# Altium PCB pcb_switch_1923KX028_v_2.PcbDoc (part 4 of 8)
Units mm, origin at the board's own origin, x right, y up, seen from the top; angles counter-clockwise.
Board outline 297.2 x 112.05 mm, 6 copper layers (Component Side, GND Layer 1, Inner Layer 1, Inner Layer 2, GND Layer 2, Solder Side), stack 1.578 mm thick; 545 components, 377 nets, 3174 pads, 1537 vias.
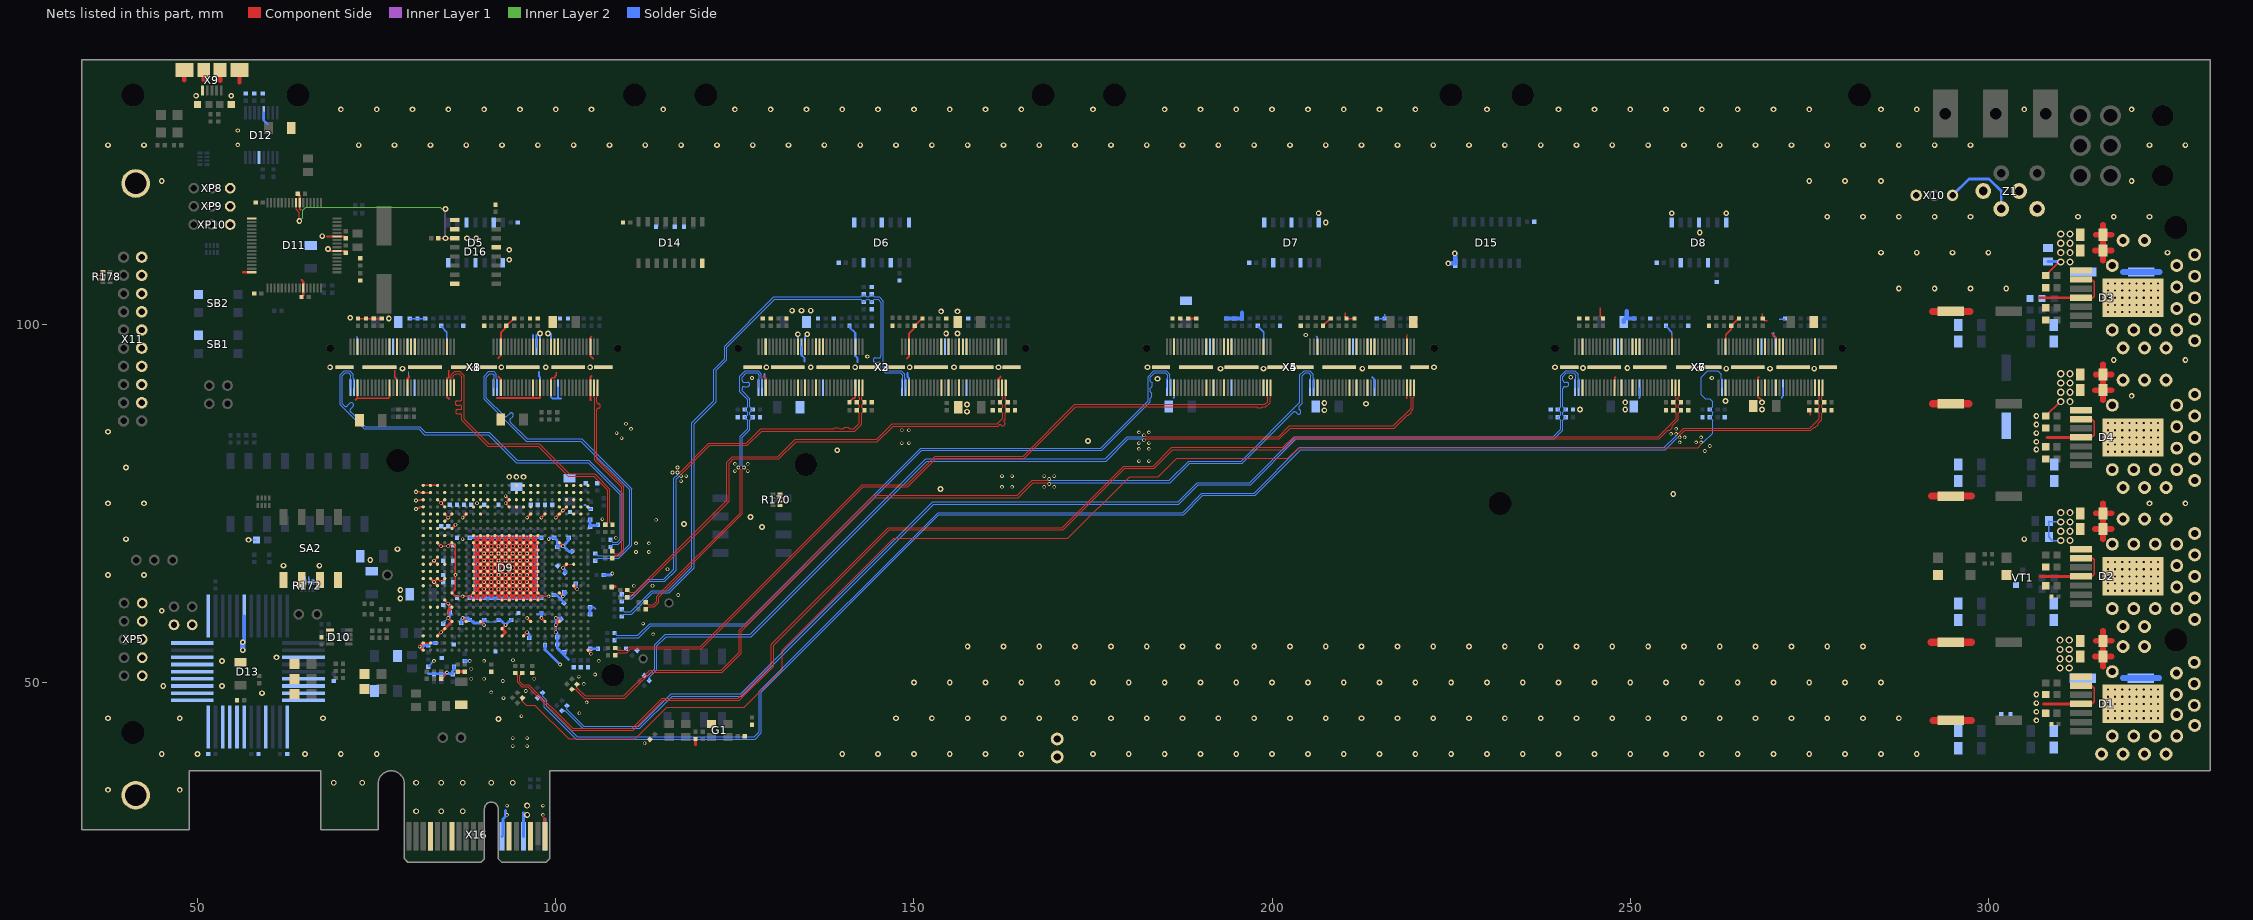
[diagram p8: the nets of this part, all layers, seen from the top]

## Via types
v1: diameter 0.8, hole 0.4, Component Side to Solder Side, tented both sides, 884 vias
v2: diameter 0.5, hole 0.3, Component Side to Solder Side, tented both sides, 269 vias
v3: diameter 1, hole 0.6, Component Side to Solder Side, tented both sides, 95 vias
v4: diameter 0.5/0.5/0.3/0.3/0.5/0.5 (per signal layer), hole 0.3, Component Side to Solder Side, tented both sides, 80 vias
v5: diameter 0.5/0.3/0.3/0.5/0.3/0.5 (per signal layer), hole 0.3, Component Side to Solder Side, tented both sides, 37 vias
v6: diameter 0.5/0.3/0.3/0.3/0.3/0.5 (per signal layer), hole 0.3, Component Side to Solder Side, tented both sides, 34 vias
v7: diameter 0.5/0.5/0.5/0.3/0.5/0.5 (per signal layer), hole 0.3, Component Side to Solder Side, tented both sides, 29 vias
v8: diameter 0.5, hole 0.3, Component Side to Solder Side, 25 vias
v9: diameter 0.5/0.3/0.5/0.3/0.3/0.5 (per signal layer), hole 0.3, Component Side to Solder Side, tented both sides, 25 vias
v10: diameter 0.5/0.5/0.3/0.5/0.5/0.5 (per signal layer), hole 0.3, Component Side to Solder Side, tented both sides, 19 vias
v11: diameter 0.6, hole 0.3, Component Side to Solder Side, tented both sides, 14 vias
v12: diameter 0.8, hole 0.5, Component Side to Solder Side, tented both sides, 11 vias
v13: diameter 0.5/0.3/0.5/0.5/0.3/0.5 (per signal layer), hole 0.3, Component Side to Solder Side, tented both sides, 7 vias
v14: diameter 0.8, hole 0.4, Component Side to Solder Side, 5 vias
v15: diameter 0.5/0.5/0.5/0.5/0.5/0.5 (per signal layer), hole 0.3, Component Side to Solder Side, tented both sides, 2 vias
v16: diameter 0.8, hole 0.5, Component Side to Solder Side, 1 vias

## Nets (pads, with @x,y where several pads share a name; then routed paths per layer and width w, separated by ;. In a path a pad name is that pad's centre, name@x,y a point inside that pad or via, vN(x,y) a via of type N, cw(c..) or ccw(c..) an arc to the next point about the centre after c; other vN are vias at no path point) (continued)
GND: C1.2 C2.2 C3.2 C4.2 C5.2 C6.2 C7.2 C8.2 C9.2 C10.2 C11.2 C12.2 C13.2 C14.2 C15.2 C16.2 C17.2 C18.1 C19.2 C20.2 C21.2 C22.2 C23.2 C24.2 C25.2 C26.2 C27.2 C28.2 C29.2 C30.2 C31.1 C32.1 C33.1 C34.1 C35.2 C36.2 C37.2 C38.2 C39.2 C40.2 C41.2 C42.2 C43.1 C44.2 C45.2 C46.2 C47.2 C50.2 C51.2 C52.2 C53.2 C56.2 C57.1 C58.2 C59.2 C61.1 C63.1 C65.2 C66.2 C69.2 C70.2 C71.2 C74.2 C75.2 C78.2 C83.2 C85.2 C94.1 C95.1 C96.1 C101.2 C102.2 C103.2 C104.2 C105.2 C106.2 C107.2 C108.2 C109.2 C110.2 C111.2 C112.2 C113.2 C114.2 C115.2 C116.1 C117.1 C118.1 C119.1 C121.1 C122.1 C123.1 C124.1 C125.2 C126.1 C127.2 C128.2 C129.2 C130.2 C131.2 C132.2 C133.2 C134.2 C135.2 C136.2 C137.2 C138.2 C139.2 C140.2 C141.2 C142.2 C143.2 C144.2 C145.2 C146.2 C147.2 C148.2 C149.2 C150.2 C151.2 C152.2 C153.2 C154.2 C155.2 C156.2 C157.2 C158.2 C159.2 C160.2 C161.2 C162.2 C163.2 C164.2 C165.2 C166.2 C167.2 C168.2 C169.2 C170.2 C171.2 C172.2 C173.2 C174.2 C175.2 C176.2 C177.2 C178.2 C179.2 C180.2 C181.2 C182.2 C183.2 C184.2 C187.2 C188.2 C189.2 C190.2 C193.2 C194.2 C195.2 C196.2 C197.2 C198.2 C199.2 C200.2 C201.2 C202.2 C203.2 C204.2 C205.2 C206.2 C207.2 C208.2 C209.2 C210.2 C211.2 C212.2 C213.2 C214.2 C215.2 C216.2 C217.2 C218.2 C219.2 C220.2 C221.2 C222.2 C223.2 C224.2 C225.2 C226.2 C227.1 C228.2 C229.2 C230.2 C231.2 C232.2 C233.2 C234.2 C235.2 C236.2 C237.2 C238.2 C239.1 D1.2 D1.4 D1.8 D2.2 D2.4 D2.8 D3.2 D3.4 D3.8 D4.2 D4.4 D4.8 D5.1 D5.4 D5.7 D5.10 D5.13 D6.1 D6.4 D6.7 D6.10 D6.13 D7.1 D7.4 D7.7 D7.10 D7.13 D8.1 D8.4 D8.7 D8.10 D8.13 D9.A1 D9.A2 D9.A3 D9.A7 D9.A8 D9.A9 D9.A14 D9.A15 D9.A16 D9.A17 D9.A21 D9.A22 D9.A23 D9.A24 D9.AA4 D9.AA12 D9.AB1 D9.AB3 D9.AB12 D9.AB15 D9.AC1 D9.AC2 D9.AD1 D9.AD24 D9.B1 D9.B2 D9.B4 D9.B8 D9.B9 D9.B14 D9.B15 D9.B16 D9.B17 D9.B20 D9.B21 D9.B22 D9.B23 D9.C1 D9.C3 D9.C4 D9.C7 D9.C8 D9.C9 D9.C10 D9.C11 D9.C13 D9.C14 D9.C15 D9.C16 D9.C20 D9.C21 D9.C22 D9.C23 D9.D1 D9.D4 D9.D8 D9.D9 D9.D10 D9.D13 D9.D14 D9.D15 D9.D16 D9.D20 D9.D21 D9.D22 D9.D23 D9.D24 D9.E1 D9.E2 D9.E3 D9.E4 D9.E5 D9.E7 D9.E9 D9.E16 D9.E18 D9.E20 D9.E22 D9.E23 D9.F1 D9.F2 D9.F3 D9.F4 D9.G2 D9.G3 D9.G4 D9.G5 D9.H1 D9.H3 D9.H4 D9.H8 D9.H9 D9.H10 D9.H11 D9.H12 D9.H13 D9.H14 D9.H15 D9.H16 D9.H17 D9.J3 D9.J5 D9.J8 D9.J9 D9.J10 D9.J11 D9.J12 D9.J13 D9.J14 D9.J15 D9.J16 D9.J17 D9.J20 D9.K8 D9.K9 D9.K10 D9.K11 D9.K12 D9.K13 D9.K14 D9.K15 D9.K16 D9.K17 D9.L1 D9.L3 D9.L8 D9.L9 D9.L10 D9.L11 D9.L12 D9.L13 D9.L14 D9.L15 D9.L16 D9.L17 D9.M1 D9.M2 D9.M3 D9.M4 D9.M8 D9.M9 D9.M10 D9.M11 D9.M12 D9.M13 D9.M14 D9.M15 D9.M16 D9.M17 D9.M21 D9.M22 D9.N1 D9.N2 D9.N3 D9.N8 D9.N9 D9.N10 D9.N11 D9.N12 D9.N13 D9.N14 D9.N15 D9.N16 D9.N17 D9.P1 D9.P2 D9.P3 D9.P4 D9.P8 D9.P9 D9.P10 D9.P11 D9.P12 D9.P13 D9.P14 D9.P15 D9.P16 D9.P17 D9.R1 D9.R3 D9.R8 D9.R9 D9.R10 D9.R11 D9.R12 D9.R13 D9.R14 D9.R15 D9.R16 D9.R17 D9.R22 D9.T5 D9.T8 D9.T9 D9.T10 D9.T11 D9.T12 D9.T13 D9.T14 D9.T15 D9.T16 D9.T17 D9.T20 D9.U4 D9.U8 D9.U9 D9.U12 D9.U13 D9.U14 D9.U15 D9.U16 D9.U17 D9.V2 D9.V3 D9.V5 D9.Y5 D9.Y7 D9.Y9 D9.Y16 D9.Y18 D9.Y20 D10.5 D11.11 D11.23 D11.27 D11.39 D11.49 D11.64 D12.5 D12.13 D13.1 D13.2 D13.3 D13.4 D13.6 D13.7 D13.8 D13.9 D13.10 D13.11 D13.12 D13.13 D13.15 D13.16 D13.21 D13.30 D13.33 D13.34 D13.35 D13.36 D13.37 D13.40 D14.8 D15.8 D16.1 D16.2 D16.8 D16.13 G1.2 pad.0@41.35,34.25 pad.0@41.35,119.65 pad.0@170,39.6 pad.0@170,42.1 pad.0@315.8,40 pad.0@317.3,42.5 pad.0@317.3,51.5 pad.0@317.3,60.3 pad.0@317.3,69.3 pad.0@317.3,79.7 pad.0@317.3,88.7 pad.0@317.3,99.2 pad.0@317.3,108.2 pad.0@318.8,40 pad.0@318.8,55 pad.0@318.8,57.8 pad.0@318.8,72.8 pad.0@318.8,77.2 pad.0@318.8,92.2 pad.0@318.8,96.7 pad.0@318.8,111.7 pad.0@320.3,42.5 pad.0@320.3,60.3 pad.0@320.3,69.3 pad.0@320.3,79.7 pad.0@320.3,99.2 pad.0@321.8,40 pad.0@321.8,55 pad.0@321.8,57.8 pad.0@321.8,72.8 pad.0@321.8,77.2 pad.0@321.8,92.2 pad.0@321.8,96.7 pad.0@321.8,111.7 pad.0@323.3,42.5 pad.0@323.3,60.3 pad.0@323.3,69.3 pad.0@323.3,79.7 pad.0@323.3,99.2 pad.0@324.8,40 pad.0@324.8,72.8 pad.0@324.8,77.2 pad.0@324.8,92.2 pad.0@324.8,96.7 pad.0@326.3,42.5 pad.0@326.3,45.5 pad.0@326.3,60.3 pad.0@326.3,63.3 pad.0@326.3,66.3 pad.0@326.3,69.3 pad.0@326.3,79.7 pad.0@326.3,82.7 pad.0@326.3,85.7 pad.0@326.3,88.7 pad.0@326.3,99.2 pad.0@326.3,102.2 pad.0@326.3,105.2 pad.0@326.3,108.2 pad.0@326.25,48.3 pad.0@326.25,51.3 pad.0@328.8,44 pad.0@328.8,58.8 pad.0@328.8,61.8 pad.0@328.8,64.8 pad.0@328.8,67.8 pad.0@328.8,70.8 pad.0@328.8,78.2 pad.0@328.8,81.2 pad.0@328.8,84.2 pad.0@328.8,87.2 pad.0@328.8,90.2 pad.0@328.8,97.7 pad.0@328.8,100.7 pad.0@328.8,103.7 pad.0@328.8,106.7 pad.0@328.8,109.7 pad.0@328.75,46.8 pad.0@328.75,49.8 pad.0@328.75,52.8 R1.2 R2.1 R3.1 R4.1 R5.1 R21.2 R22.2 R23.2 R24.2 R35.2 R38.2 R39.2 R40.2 R42.2 R44.2 R45.2 R46.2 R48.2 R50.2 R52.2 R54.2 R56.2 R58.2 R62.2 R63.2 R64.2 R65.2 R70.2 R71.2 R78.2 R79.2 R80.2 R81.2 R82.2 R83.2 R86.2 R87.2 R94.1 R95.1 R96.2 R97.2 R105.2 R106.2 R107.2 R108.2 R114.2 R115.2 R118.1 R119.1 R120.1 R121.2 R123.2 R125.2 R127.2 R128.2 R129.2 R130.2 R132.2 R133.2 R135.2 R136.2 R137.2 R144.2 R146.2 R148.2 R149.2 R151.2 R155.2 R157.2 R159.2 R160.1 R166.2 R168.2 R170.1 R170.2 R170.3 R170.4 R172.5 R172.6 R172.7 R172.8 R178.1 R178.2 R178.3 R180.1 R187.2 R188.2 R190.2 R191.2 R192.2 R193.2 R194.2 R195.2 R197.2 R198.2 R200.2 R201.2 R202.2 R203.2 R205.2 R207.2 R214.2 R215.2 R216.2 R220.2 R221.2 R222.2 R223.2 R224.2 SA2.1 SA2.2 SA2.3 SA2.4 SB1.3 SB2.3 VD1.2 VD4.2 VD5.2 VD6.2 VD7.2 VD8.2 VD9.2 VT1.2 X1.5 X1.6 X1.23 X1.24 X1.27 X1.28 X1.33 X1.34 X1.36 X1.38 X1.55 X1.56 X1.65 X1.66 X1.83 X1.84 X1.87 X1.88 X1.93 X1.94 X1.96 X1.98 X1.115 X1.116 X1.121 X1.122 X1.123 X1.124 X1.125 X1.126 X1.127 X1.128 X2.5 X2.6 X2.23 X2.24 X2.27 X2.28 X2.33 X2.34 X2.36 X2.38 X2.55 X2.56 X2.65 X2.66 X2.83 X2.84 X2.87 X2.88 X2.93 X2.94 X2.96 X2.98 X2.115 X2.116 X2.121 X2.122 X2.123 X2.124 X2.125 X2.126 X2.127 X2.128 X3.5 X3.6 X3.23 X3.24 X3.27 X3.28 X3.33 X3.34 X3.36 X3.38 X3.55 X3.56 X3.65 X3.66 X3.83 X3.84 X3.87 X3.88 X3.93 X3.94 X3.96 X3.98 X3.115 X3.116 X3.121 X3.122 X3.123 X3.124 X3.125 X3.126 X3.127 X3.128 X4.5 X4.6 X4.23 X4.24 X4.27 X4.28 X4.33 X4.34 X4.36 X4.38 X4.55 X4.56 X4.65 X4.66 X4.83 X4.84 X4.87 X4.88 X4.93 X4.94 X4.96 X4.98 X4.115 X4.116 X4.121 X4.122 X4.123 X4.124 X4.125 X4.126 X4.127 X4.128 X5.5 X5.6 X5.23 X5.24 X5.27 X5.28 X5.33 X5.34 X5.36 X5.38 X5.55 X5.56 X5.65 X5.66 X5.83 X5.84 X5.87 X5.88 X5.93 X5.94 X5.96 X5.98 X5.115 X5.116 X5.121 X5.122 X5.123 X5.124 X5.125 X5.126 X5.127 X5.128 X6.5 X6.6 X6.23 X6.24 X6.27 X6.28 X6.33 X6.34 X6.36 X6.38 X6.55 X6.56 X6.65 X6.66 X6.83 X6.84 X6.87 X6.88 X6.93 X6.94 X6.96 X6.98 X6.115 X6.116 X6.121 X6.122 X6.123 X6.124 X6.125 X6.126 X6.127 X6.128 X7.5 X7.6 X7.23 X7.24 X7.27 X7.28 X7.33 X7.34 X7.36 X7.38 X7.55 X7.56 X7.65 X7.66 X7.83 X7.84 X7.87 X7.88 X7.93 X7.94 X7.96 X7.98 X7.115 X7.116 X7.121 X7.122 X7.123 X7.124 X7.125 X7.126 X7.127 X7.128 X8.5 X8.6 X8.23 X8.24 X8.27 X8.28 X8.33 X8.34 X8.36 X8.38 X8.55 X8.56 X8.65 X8.66 X8.83 X8.84 X8.87 X8.88 X8.93 X8.94 X8.96 X8.98 X8.115 X8.116 X8.121 X8.122 X8.123 X8.124 X8.125 X8.126 X8.127 X8.128 X9.5 X9.6 X9.7 X9.8 X9.9 X10.3 X11.4 X11.6 X11.8 X11.10 X11.12 X11.14 X11.16 X11.18 X11.20 X16.A4 X16.A12 X16.A15 X16.A18 X16.B4 X16.B7 X16.B13 X16.B16 X16.B18 XP1.2 XP3.2 XP5.2 XP5.4 XP5.6 XP5.8 XP5.10 XP8.3 XP9.3 XP10.3 Z1.4 Z1.5 Z1.6 | length 694.4
  Component Side w0.15: D9.M21@101.5,66.5 D9.M22@102.5,66.5 ; R170.2@131.3,75.25 132.05,75.25 ; R170.3@131.3,75.75 132.05,75.75
  Component Side w0.2: 36.05,106.35 R178.3@36.8,106.35 ; 36.05,106.85 R178.2@36.8,106.85 ; D11.39@64.25,116.95 64.25,116.15 64.5,115.9 ; SA2.3@67,64.37 SA2.3@67.07,64.3 ; 72,89.4 72.3,89.7 ; X1.5@72.315,91.135 72.315,89.715 72.3,89.7 ; R128.2@72.4,100.8 R129.2@73.5,100.8 R130.2@74.6,100.8 R132.2@75.7,100.8 ; X1.23@76.815,91.135 76.815,89.915 76.6,89.7 72.3,89.7 ; 77.5,93.6 77.5,92.6 77.815,92.285 X1.27@77.815,91.135 ; v11(80.5,74.2) 80.6,74.3 80.9,74.3 81.1,74.5 D9.D1@81.5,74.5 ; v11(80.5,75.4) 81,75.4 81.1,75.5 D9.C1@81.5,75.5 ; v11(80.5,76.6) 81,76.6 81.1,76.5 D9.B1@81.5,76.5 D9.B2@82.5,76.5 ; D9.AC1@81.5,55.5 D9.AC2@82.5,55.5 ; D9.A1@81.5,77.5 D9.A2@82.5,77.5 D9.A3@83.5,77.5 ; D9.M2@82.5,66.5 D9.L3@83.5,67.5 ; v7(83,67) D9.M3@83.5,66.5 ; D9.P3@83.5,64.5 83.9,64.1 84.1,64.1 D9.P4@84.5,64.5 ; D9.C3@83.5,75.5 v2(84,75) ; R144.2@84,50.5 84.1,50.5 84.6,51 84.6,51.2 v7(84.8,51.4) ; v7(84,69) v7(85,69) ; D9.U4@84.5,61.5 v7(85,61) ; D9.F4@84.5,72.5 v7(85,73) ; D9.E4@84.5,73.5 v7(85,73) ; D9.D4@84.5,74.5 v2(84,75) ; D9.C4@84.5,75.5 v2(84,75) ; v4(85,59) 85,60 ; 85.035,93.6 85.035,92.635 84.815,92.415 X1.55@84.815,91.135 84.815,89.885 85.2,89.5 ; D9.J5@85.5,69.5 86,69 v4(86,65) 86,63 D9.T5@85.5,62.5 86,62 v4(87,62) 88,62 ; D9.E5@85.5,73.5 v7(85,73) ; D9.U8@88.5,61.5 88,62 ; D9.T8@88.5,62.5 88,62 ; v2(93,76) D9.C13@93.5,75.5 v2(93,75) D9.D13@93.5,74.5 ; R42.2@93.1,99.8 94.1,100.8 R133.2@94.2,100.8 ; D9.U17@97.5,61.5 98,62 ; D9.T17@97.5,62.5 98,62 ; v4(99,62) 98,62 ; X1.93@99.32,91.135 99.32,92.367 99.5,92.547 99.8,92.547 100.1,92.847 100.1,93.3 ; v4(100,57) v4(100,58) ; 105,98.3 104.82,98.12 X1.116@104.82,96.865 104.82,95.58 105.2,95.2 105.3,95.2 ; R21.2@141,89.2 141.5,89.7 141.7,89.7 141.815,89.815 X2.55@141.815,91.135 ; R48.2@150.1,99.8 151.1,100.8 R149.2@151.2,100.8 ; R79.2@207.1,99.8 208.1,100.8 R197.2@208.2,100.8 ; 210.2,101.6 210.2,101 R198.2@210.4,100.8 R201.2@211.5,100.8 ; 218.82,89.58 X4.115@218.82,91.135 ; X4.116@218.82,96.865 218.82,98.42 218.9,98.5 ; 245.8,102.3 245.8,101.2 R193.2@246.2,100.8 ; X6.23@247.815,91.135 247.815,92.515 248,92.7 ; X6.56@255.815,96.865 255.815,98.415 255.9,98.5 ; X6.66@263.32,96.865 263.32,98.52 264.1,99.3 R83.2@264.1,99.8 265.1,100.8 R200.2@265.2,100.8 ; 268,92.7 267.82,92.52 X6.83@267.82,91.135 267.82,89.88 268.2,89.5 ; 268.4,101.5 268.4,100.9 R203.2@268.5,100.8 268.8,100.5 269.1,100.5 ; R86.2@275,88 275.1,87.9 275.1,87.3 ; D3.2@312.86,106.3 D3.2@312.92,106.24 314.46,106.24 314.8,105.9 314.8,103.9 314.5,103.6 313.02,103.6 D3.4@312.92,103.7 ; D1.4@312.92,47 314.5,47 314.8,47.3 314.8,49.2 314.46,49.54 D1.2@312.92,49.54 ; D2.4@312.92,64.8 314.5,64.8 314.8,65.1 314.8,67.1 314.56,67.34 D2.2@312.92,67.34 ; D4.4@312.92,84.2 314.4,84.2 314.8,84.6 314.8,86.4 314.46,86.74 D4.2@312.92,86.74
  Component Side w0.28: X1.33@79.315,91.135 79.315,92.415 79.5,92.6 79.5,92.8 ; 91.8,89.7 97.82,89.7 X1.87@97.82,91.135 ; 92,92.7 92.32,92.38 X1.65@92.32,91.135 ; 92,95.3 92.32,95.62 X1.66@92.32,96.865 92.32,98.82 93.1,99.6 R42.2@93.1,99.8 ; 96.82,89.7 X1.83@96.82,91.135 ; 104.9,89.4 104.82,89.48 X1.115@104.82,91.135 104.82,92.62 105,92.8 ; 129,92.7 129.315,92.385 X2.5@129.315,91.135 ; 149,95.2 149.32,95.52 X2.66@149.32,96.865 149.32,98.72 150,99.4 150,99.7 R48.2@150.1,99.8 ; X2.115@161.82,91.135 161.82,92.42 162.1,92.7 ; R191.2@188.3,100.8 R194.2@189.4,100.8 ; 269.8,98.7 270.32,98.18 X6.94@270.32,96.865
  Component Side w0.3: 56.35,107.25 D11.64@57.55,107.25 ; C126.1@64,118.2 64.25,117.95 D11.39@64.25,116.95 ; C123.1@64.5,103.8 64.75,104.05 D11.11@64.75,105.05 64.75,105.95 64.5,106.2 ; 68.05,112.25 D11.27@69.45,112.25 70.45,112.25 C119.1@70.7,112 ; v1(68.2,110.5) 68.45,110.25 D11.23@69.45,110.25 70.45,110.25 C118.1@70.7,110
  Component Side w0.4: D9.AD1@81.5,54.5 v2(81,55) D9.AC1@81.5,55.5 ; D9.P2@82.5,64.5 v7(83,64) ; D9.AB3@83.5,56.5 D9.Y5@85.5,58.5 v4(85,59) ; D9.R3@83.5,63.5 v7(83,64) ; D9.P3@83.5,64.5 v7(83,64) ; D9.J3@83.5,69.5 v7(84,69) ; 85,60 D9.V5@85.5,60.5 v7(85,61) ; v7(85,69) D9.J5@85.5,69.5 ; D9.G5@85.5,71.5 v4(86,72) ; C214.2@86.3,51.5 C205.2@87.3,51.5 ; v4(87,59) D9.Y7@87.5,58.5 ; v4(87,73) D9.E7@87.5,73.5 ; D9.U8@88.5,61.5 89,62 ; D9.H8@88.5,70.5 89,70 ; D9.Y9@89.5,58.5 v4(90,58) ; v4(91,64) D9.R11@91.5,63.5 ; v4(91,66) D9.N11@91.5,65.5 ; v4(91,67) D9.M11@91.5,66.5 ; v4(91,68) D9.L11@91.5,67.5 ; D9.AB12@92.5,56.5 93,57 D9.AA12@92.5,57.5 v4(93,58) ; D9.AB15@95.5,56.5 v4(96,57) ; v4(96,59) D9.Y16@96.5,58.5 ; v4(96,67) D9.M16@96.5,66.5 ; v4(96,69) D9.K16@96.5,68.5 ; v4(96,73) D9.E16@96.5,73.5 ; D9.U17@97.5,61.5 97,62 ; D9.H17@97.5,70.5 97,70 ; v4(98,59) D9.Y18@98.5,58.5 ; v4(98,73) D9.E18@98.5,73.5 ; 98.4,31 98.4,28.6 X16.B18@98.5,28.5 ; v4(100,58) D9.Y20@100.5,58.5 v4(100,59) ; v7(100,73) v2(101,74) D9.D21@101.5,74.5 ; D9.T20@100.5,62.5 v4(101,62) ; D9.J20@100.5,69.5 v4(101,69) ; v4(101,66) D9.M21@101.5,66.5 ; D9.R22@102.5,63.5 v4(103,63) ; D9.AD24@104.5,54.5 v2@104.9,54.1 ; C218.2@107.8,63.3 107.9,63.4 108.3,63.4 ; 119.5,41.3 C94.1@119.5,42.1 ; 307.2,64.8 D2.4@312.92,64.8 ; 307.2,103.7 D3.4@312.92,103.7 ; 307.7,47 D1.4@312.92,47 ; 308.2,84.2 D4.4@312.92,84.2 ; 89,62 D9.T8@88.5,62.5 89,63 ; 89,62 D9.U9@89.5,61.5 90,62 ; 89,62 D9.T9@89.5,62.5 ; 89,63 D9.R9@89.5,63.5 ; 89,63 D9.R8@88.5,63.5 89,64 ; 89,63 D9.T9@89.5,62.5 ; 89,64 D9.P8@88.5,64.5 89,65 ; 89,64 D9.R9@89.5,63.5 ; 89,64 D9.P9@89.5,64.5 ; 89,65 D9.N8@88.5,65.5 89,66 ; 89,65 D9.P9@89.5,64.5 ; 89,65 D9.N9@89.5,65.5 ; 89,66 D9.M9@89.5,66.5 ; 89,66 D9.M8@88.5,66.5 89,67 ; 89,66 D9.N9@89.5,65.5 ; 89,67 D9.M9@89.5,66.5 ; 89,67 D9.L8@88.5,67.5 89,68 ; 89,67 D9.L9@89.5,67.5 ; 89,68 D9.K8@88.5,68.5 89,69 ; 89,68 D9.L9@89.5,67.5 ; 89,68 D9.K9@89.5,68.5 ; 89,69 D9.J8@88.5,69.5 89,70 ; 89,69 D9.K9@89.5,68.5 ; 89,69 D9.J9@89.5,69.5 ; 89,70 D9.H9@89.5,70.5 90,70 ; 89,70 D9.J9@89.5,69.5 ; D9.T9@89.5,62.5 90,62 ; D9.T9@89.5,62.5 v4(90,63) ; D9.R9@89.5,63.5 v4(90,63) ; D9.R9@89.5,63.5 v4(90,64) ; D9.P9@89.5,64.5 v4(90,64) ; D9.P9@89.5,64.5 v4(90,65) ; D9.N9@89.5,65.5 v4(90,66) ; D9.N9@89.5,65.5 v4(90,65) ; D9.M9@89.5,66.5 v4(90,66) ; D9.M9@89.5,66.5 v4(90,67) ; D9.L9@89.5,67.5 v4(90,68) ; D9.L9@89.5,67.5 v4(90,67) ; D9.K9@89.5,68.5 v4(90,69) ; D9.K9@89.5,68.5 v4(90,68) ; D9.J9@89.5,69.5 v4(90,69) ; D9.J9@89.5,69.5 90,70 ; 90,62 D9.T10@90.5,62.5 ; v4(90,63) D9.R10@90.5,63.5 ; v4(90,63) D9.T10@90.5,62.5 ; v4(90,64) D9.R10@90.5,63.5 ; v4(90,64) D9.P10@90.5,64.5 ; v4(90,65) D9.P10@90.5,64.5 ; v4(90,65) D9.N10@90.5,65.5 ; v4(90,66) D9.M10@90.5,66.5 ; v4(90,66) D9.N10@90.5,65.5 ; v4(90,67) D9.L10@90.5,67.5 ; v4(90,67) D9.M10@90.5,66.5 ; v4(90,68) D9.K10@90.5,68.5 ; v4(90,68) D9.L10@90.5,67.5 ; v4(90,69) D9.J10@90.5,69.5 ; v4(90,69) D9.K10@90.5,68.5 ; 90,70 D9.J10@90.5,69.5 ; 90,70 D9.H10@90.5,70.5 91,70 ; D9.T10@90.5,62.5 v4(91,63) ; D9.T10@90.5,62.5 91,62 D9.T11@91.5,62.5 ; D9.R10@90.5,63.5 v4(91,64) ; D9.R10@90.5,63.5 v4(91,63) ; D9.P10@90.5,64.5 v4(91,65) ; D9.P10@90.5,64.5 v4(91,64) ; D9.N10@90.5,65.5 v4(91,65) ; D9.N10@90.5,65.5 v4(91,66) ; D9.M10@90.5,66.5 v4(91,66) ; D9.M10@90.5,66.5 v4(91,67) ; D9.L10@90.5,67.5 v4(91,68) ; D9.L10@90.5,67.5 v4(91,67) ; D9.K10@90.5,68.5 v4(91,69) ; D9.K10@90.5,68.5 v4(91,68) ; D9.J10@90.5,69.5 91,70 ; D9.J10@90.5,69.5 v4(91,69) ; v4(91,63) D9.R11@91.5,63.5 ; v4(91,63) D9.T11@91.5,62.5 ; v4(91,64) D9.P11@91.5,64.5 ; v4(91,65) D9.N11@91.5,65.5 ; v4(91,65) D9.P11@91.5,64.5 ; v4(91,66) D9.M11@91.5,66.5 ; v4(91,67) D9.L11@91.5,67.5 ; v4(91,68) D9.K11@91.5,68.5 ; v4(91,69) D9.J11@91.5,69.5 ; v4(91,69) D9.K11@91.5,68.5 ; 91,70 D9.H11@91.5,70.5 92,70 ; 91,70 D9.J11@91.5,69.5 ; D9.T11@91.5,62.5 v4(92,63) ; D9.T11@91.5,62.5 92,62 ; D9.R11@91.5,63.5 v4(92,64) ; D9.R11@91.5,63.5 v4(92,63) ; D9.P11@91.5,64.5 v4(92,65) ; D9.P11@91.5,64.5 v4(92,64) ; D9.N11@91.5,65.5 v4(92,66) ; D9.N11@91.5,65.5 v4(92,65) ; D9.M11@91.5,66.5 v4(92,67) ; D9.M11@91.5,66.5 v4(92,66) ; D9.L11@91.5,67.5 v4(92,67) ; D9.L11@91.5,67.5 v4(92,68) ; D9.K11@91.5,68.5 v4(92,68) ; D9.K11@91.5,68.5 v4(92,69) ; D9.J11@91.5,69.5 92,70 ; D9.J11@91.5,69.5 v4(92,69) ; 92,62 D9.T12@92.5,62.5 ; 92,62 D9.U12@92.5,61.5 93,62 ; v4(92,63) D9.R12@92.5,63.5 ; v4(92,63) D9.T12@92.5,62.5 ; v4(92,64) D9.R12@92.5,63.5 ; v4(92,64) D9.P12@92.5,64.5 ; v4(92,65) D9.N12@92.5,65.5 ; v4(92,65) D9.P12@92.5,64.5 ; v4(92,66) D9.M12@92.5,66.5 ; v4(92,66) D9.N12@92.5,65.5 ; v4(92,67) D9.L12@92.5,67.5 ; v4(92,67) D9.M12@92.5,66.5 ; v4(92,68) D9.L12@92.5,67.5 ; v4(92,68) D9.K12@92.5,68.5 ; v4(92,69) D9.K12@92.5,68.5 ; v4(92,69) D9.J12@92.5,69.5 ; 92,70 D9.H12@92.5,70.5 93,70 ; 92,70 D9.J12@92.5,69.5 ; D9.T12@92.5,62.5 v4(93,63) ; D9.T12@92.5,62.5 93,62 ; D9.R12@92.5,63.5 v4(93,64) ; D9.R12@92.5,63.5 v4(93,63) ; D9.P12@92.5,64.5 v4(93,65) ; D9.P12@92.5,64.5 v4(93,64) ; D9.N12@92.5,65.5 v4(93,66) ; D9.N12@92.5,65.5 v4(93,65) ; D9.M12@92.5,66.5 v4(93,66) ; D9.M12@92.5,66.5 v4(93,67) ; D9.L12@92.5,67.5 v4(93,67) ; D9.L12@92.5,67.5 v4(93,68) ; D9.K12@92.5,68.5 v4(93,68) ; D9.K12@92.5,68.5 v4(93,69) ; D9.J12@92.5,69.5 v4(93,69) ; D9.J12@92.5,69.5 93,70 ; 93,62 D9.U13@93.5,61.5 94,62 ; 93,62 D9.T13@93.5,62.5 ; v4(93,63) D9.T13@93.5,62.5 ; v4(93,63) D9.R13@93.5,63.5 ; v4(93,64) D9.P13@93.5,64.5 ; v4(93,64) D9.R13@93.5,63.5 ; v4(93,65) D9.P13@93.5,64.5 ; v4(93,65) D9.N13@93.5,65.5 ; v4(93,66) D9.N13@93.5,65.5 ; v4(93,66) D9.M13@93.5,66.5 ; v4(93,67) D9.L13@93.5,67.5 ; v4(93,67) D9.M13@93.5,66.5 ; v4(93,68) D9.K13@93.5,68.5 ; v4(93,68) D9.L13@93.5,67.5 ; v4(93,69) D9.J13@93.5,69.5 ; v4(93,69) D9.K13@93.5,68.5 ; 93,70 D9.J13@93.5,69.5 ; 93,70 D9.H13@93.5,70.5 94,70 ; D9.T13@93.5,62.5 94,62 ; D9.T13@93.5,62.5 v4(94,63) ; D9.R13@93.5,63.5 v4(94,63) ; D9.R13@93.5,63.5 v4(94,64) ; D9.P13@93.5,64.5 v4(94,65) ; D9.P13@93.5,64.5 v4(94,64) ; D9.N13@93.5,65.5 v4(94,65) ; D9.N13@93.5,65.5 v4(94,66) ; D9.M13@93.5,66.5 v4(94,67) ; D9.M13@93.5,66.5 v4(94,66) ; D9.L13@93.5,67.5 v4(94,68) ; D9.L13@93.5,67.5 v4(94,67) ; D9.K13@93.5,68.5 v4(94,68) ; D9.K13@93.5,68.5 v4(94,69) ; D9.J13@93.5,69.5 v4(94,69) ; D9.J13@93.5,69.5 94,70 ; 94,62 D9.U14@94.5,61.5 95,62 ; 94,62 D9.T14@94.5,62.5 ; v4(94,63) D9.T14@94.5,62.5 ; v4(94,63) D9.R14@94.5,63.5 ; v4(94,64) D9.P14@94.5,64.5 ; v4(94,64) D9.R14@94.5,63.5 ; v4(94,65) D9.N14@94.5,65.5 ; v4(94,65) D9.P14@94.5,64.5 ; v4(94,66) D9.N14@94.5,65.5 ; v4(94,66) D9.M14@94.5,66.5 ; v4(94,67) D9.M14@94.5,66.5 ; v4(94,67) D9.L14@94.5,67.5 ; v4(94,68) D9.K14@94.5,68.5 ; v4(94,68) D9.L14@94.5,67.5 ; v4(94,69) D9.J14@94.5,69.5 ; v4(94,69) D9.K14@94.5,68.5 ; 94,70 D9.J14@94.5,69.5 ; 94,70 D9.H14@94.5,70.5 95,70 ; D9.T14@94.5,62.5 v4(95,63) ; D9.T14@94.5,62.5 95,62 ; D9.R14@94.5,63.5 v4(95,64) ; D9.R14@94.5,63.5 v4(95,63) ; D9.P14@94.5,64.5 v4(95,65) ; D9.P14@94.5,64.5 v4(95,64) ; D9.N14@94.5,65.5 v4(95,66) ; D9.N14@94.5,65.5 v4(95,65) ; D9.M14@94.5,66.5 v4(95,67) ; D9.M14@94.5,66.5 v4(95,66) ; D9.L14@94.5,67.5 v4(95,68) ; D9.L14@94.5,67.5 v4(95,67) ; D9.K14@94.5,68.5 v4(95,68) ; D9.K14@94.5,68.5 v4(95,69) ; D9.J14@94.5,69.5 95,70 ; D9.J14@94.5,69.5 v4(95,69) ; 95,62 D9.U15@95.5,61.5 96,62 ; 95,62 D9.T15@95.5,62.5 ; v4(95,63) D9.R15@95.5,63.5 ; v4(95,63) D9.T15@95.5,62.5 ; v4(95,64) D9.P15@95.5,64.5 ; v4(95,64) D9.R15@95.5,63.5 ; v4(95,65) D9.N15@95.5,65.5 ; v4(95,65) D9.P15@95.5,64.5 ; v4(95,66) D9.M15@95.5,66.5 ; v4(95,66) D9.N15@95.5,65.5 ; v4(95,67) D9.L15@95.5,67.5 ; v4(95,67) D9.M15@95.5,66.5 ; v4(95,68) D9.K15@95.5,68.5 ; v4(95,68) D9.L15@95.5,67.5 ; v4(95,69) D9.K15@95.5,68.5 ; v4(95,69) D9.J15@95.5,69.5 ; 95,70 D9.H15@95.5,70.5 96,70 ; 95,70 D9.J15@95.5,69.5 ; D9.T15@95.5,62.5 96,62 ; D9.T15@95.5,62.5 v4(96,63) ; D9.R15@95.5,63.5 v4(96,64) ; D9.R15@95.5,63.5 v4(96,63) ; D9.P15@95.5,64.5 v4(96,65) ; D9.P15@95.5,64.5 v4(96,64) ; D9.N15@95.5,65.5 v4(96,66) ; D9.N15@95.5,65.5 v4(96,65) ; D9.M15@95.5,66.5 v4(96,67) ; D9.M15@95.5,66.5 v4(96,66) ; D9.L15@95.5,67.5 v4(96,68) ; D9.L15@95.5,67.5 v4(96,67) ; D9.K15@95.5,68.5 v4(96,69) ; D9.K15@95.5,68.5 v4(96,68) ; D9.J15@95.5,69.5 v4(96,69) ; D9.J15@95.5,69.5 96,70 ; 96,62 D9.U16@96.5,61.5 97,62 ; 96,62 D9.T16@96.5,62.5 ; v4(96,63) D9.T16@96.5,62.5 ; v4(96,63) D9.R16@96.5,63.5 ; v4(96,64) D9.P16@96.5,64.5 ; v4(96,64) D9.R16@96.5,63.5 ; v4(96,65) D9.N16@96.5,65.5 ; v4(96,65) D9.P16@96.5,64.5 ; v4(96,66) D9.M16@96.5,66.5 ; v4(96,66) D9.N16@96.5,65.5 ; v4(96,67) D9.L16@96.5,67.5 ; v4(96,68) D9.K16@96.5,68.5 ; v4(96,68) D9.L16@96.5,67.5 ; v4(96,69) D9.J16@96.5,69.5 ; 96,70 D9.J16@96.5,69.5 ; 96,70 D9.H16@96.5,70.5 97,70 ; D9.T16@96.5,62.5 97,62 ; D9.T16@96.5,62.5 97,63 ; D9.R16@96.5,63.5 97,63 ; D9.R16@96.5,63.5 97,64 ; D9.P16@96.5,64.5 97,65 ; D9.P16@96.5,64.5 97,64 ; D9.N16@96.5,65.5 97,66 ; D9.N16@96.5,65.5 97,65 ; D9.M16@96.5,66.5 97,67 ; D9.M16@96.5,66.5 97,66 ; D9.L16@96.5,67.5 97,68 ; D9.L16@96.5,67.5 97,67 ; D9.K16@96.5,68.5 97,69 ; D9.K16@96.5,68.5 97,68 ; D9.J16@96.5,69.5 97,70 ; D9.J16@96.5,69.5 97,69 ; 97,62 D9.T17@97.5,62.5 97,63 ; 97,63 D9.R17@97.5,63.5 97,64 ; 97,64 D9.P17@97.5,64.5 97,65 ; 97,65 D9.N17@97.5,65.5 97,66 ; 97,66 D9.M17@97.5,66.5 97,67 ; 97,67 D9.L17@97.5,67.5 97,68 ; 97,68 D9.K17@97.5,68.5 97,69 ; 97,69 D9.J17@97.5,69.5 97,70
  Component Side w0.6: 48.15,134.05 X9.9@48.15,135.5 ; 50.85,134.05 X9.8@50.85,135.5 ; 53.15,133.95 X9.7@53.15,135.5 ; 55.85,133.75 X9.6@55.85,135.5
  Component Side w0.8: 314.9,53.6 317.2,53.6 ; 314.9,71.4 317.2,71.4 ; 314.9,90.8 317.2,90.8 ; 314.9,110.3 317.2,110.3 ; 315,55.8 317.2,55.8 ; 315,73.6 317.2,73.6 ; 315,93 317.2,93 ; 315,112.5 317.2,112.5 ; 316,52.2 C38.2@316,53.6 C37.2@316,55.8 316,57.2 ; 316,70 C47.2@316,73.6 316,75 ; 316,89.4 C70.2@316,93 316,94.4 ; 316,108.9 C59.2@316,110.3 C58.2@316,112.5 316,113.9
  Component Side w1: 292,55.6 C69.2@294.75,55.6 297.6,55.6 ; 292.1,76 C83.2@294.75,76 297.6,76 ; 292.2,88.9 C190.2@294.75,88.9 297.3,88.9 ; 292.2,101.8 C56.2@294.75,101.8 297.4,101.8 ; 292.3,44.7 C45.2@294.75,44.7 297.6,44.7
  Solder Side w0.15: v1(57.1,69.9) R160.1@58.2,69.9 ; 77.5,93.4 77.5,92.7 77.81,92.39 X8.93@77.81,91.135 ; X8.87@79.31,91.135 79.31,92.41 79.5,92.6 79.5,93.4 ; R168.2@84.3,58.2 84.3,58.3 v4(85,59) ; C181.2@90,58.8 90.3,58.5 91.7,58.5 C234.2@92,58.8
  Solder Side w0.2: R172.7@65.05,64 65.05,64.75 ; R172.6@65.55,64 65.55,64.75 ; 72.2,98.3 72.31,98.19 X8.116@72.31,96.865 ; R224.2@79.6,100.8 R222.2@80.7,100.8 R220.2@81.8,100.8 ; C238.2@82.2,52.2 v7(83,53) ; R108.2@84,99.8 84,99.7 84.81,98.89 X8.66@84.81,96.865 ; 85.1,89.6 84.81,89.89 X8.65@84.81,91.135 84.81,92.41 85.1,92.7 ; 97.3,59.5 97.8,59.5 C165.2@98,59.7 ; C207.2@104.8,60.5 105.3,60.5 105.6,60.2 ; 186.2,89.7 186.31,89.81 X5.115@186.31,91.135 ; R81.2@198,99.8 198,99.7 198.81,98.89 X5.66@198.81,96.865 ; 206.2,98.3 206.315,98.185 X5.56@206.315,96.865 ; 213.9,92.7 214.315,92.285 X5.23@214.315,91.135 ; R195.2@214.6,100.8 R192.2@215.7,100.8 215.7,101.4 ; 251.2,89.7 251.31,89.81 X7.83@251.31,91.135 ; R106.2@255,99.8 255,99.7 255.81,98.89 X7.66@255.81,96.865 ; 270.8,100.7 271.5,100.7 R215.2@271.6,100.8 R215.2@271.5,100.8 ; 271.1,89.7 271.315,89.915 X7.23@271.315,91.135
  Solder Side w0.28: X8.38@96.815,96.865 96.815,98.515 ; X8.36@97.315,96.865 97.315,98.485 ; 97.65,93.35 97.65,92.75 97.815,92.585 X8.33@97.815,91.135 ; X8.34@97.815,96.865 v1@97.815,98.685 ; X8.27@99.315,91.135 99.315,89.885 99.6,89.6 100.315,89.6 ; X8.28@99.315,96.865 99.315,98.615 ; X8.23@100.315,91.135 100.315,89.6 ; 100.7,89.6 100.315,89.6 ; 104,74.8 104.1,74.8 104.7,74.2 C180.2@104.9,74.2 ; 129.13,93.07 129.13,92.67 129.31,92.49 X3.115@129.31,91.135 ; X3.98@133.81,96.865 v1@133.81,98.59 ; X3.96@134.31,96.865 134.31,95.69 134.7,95.3 134.7,94.8 ; X3.94@134.81,96.865 134.81,98.31 v1(135.1,98.6) ; R38.2@141,99.8 141,99.6 141.81,98.79 X3.66@141.81,96.865 141.81,95.59 142.1,95.3 142.1,94.7 ; 149.13,93.17 149.13,92.67 149.315,92.485 X3.55@149.315,91.135 ; 270,98.8 270,98.4 270.315,98.085 X7.28@270.315,96.865
  Solder Side w0.35: D12.13@59.217,129.524 59.217,128.483 59.7,128
  Solder Side w0.4: v2(81,55) 81.5,55 81.7,55.2 C237.2@82.2,55.2 82.5,55.5 C203.2@83.2,55.5 ; 82.2,51.2 v7@84.8,51.2 ; v7(84.8,51.4) v7@84.8,51.2 ; v4(85,59) 85.2,59.2 C159.2@85.2,59.8 85.2,60.8 v7(85,61) ; C194.2@85.8,52.2 85.8,51.8 85.6,51.6 85.6,51.2 v7@84.8,51.2 ; C193.2@86.8,58.3 86.8,58.8 v4(87,59) 87.8,59 88,58.8 88.049,58.8 88.549,58.3 89.7,58.3 ; C198.2@87.3,53 v4(88,53) ; C127.2@88,61.8 C142.2@89,61.8 C105.2@90,61.8 C128.2@91,61.8 C144.2@92,61.8 C107.2@93,61.8 C129.2@94,61.8 C152.2@95,61.8 C106.2@96,61.8 C130.2@97,61.8 C143.2@98,61.8 ; C137.2@88,70.2 C154.2@89,70.2 C115.2@90,70.2 C136.2@91,70.2 C153.2@92,70.2 C114.2@93,70.2 C138.2@94,70.2 C151.2@95,70.2 C113.2@96,70.2 C135.2@97,70.2 C150.2@98,70.2 ; C109.2@88.8,63 C145.2@88.8,64 C131.2@88.8,65 C141.2@88.8,66 C111.2@88.8,67 C140.2@88.8,68 C133.2@88.8,69 ; v4(90,58) 89.7,58.3 ; C181.2@90,58.8 90,58.6 89.7,58.3 ; C234.2@92,58.8 92.2,58.8 v4(93,58) C178.2@93.8,58.8 ; X16.A12@92.5,28.5 92.65,28.65 92.65,30.95 93,31.3 93,32.1 ; X16.A15@95.5,28.5 95.5,31.8 ; v4(96,57) 96.3,56.7 C219.2@96.3,56.2 ; C110.2@97.2,63 C146.2@97.2,64 C132.2@97.2,65 C147.2@97.2,66 C112.2@97.2,67 C148.2@97.2,68 C134.2@97.2,69 ; v4(98,59) C165.2@98,59.7 C165.2@98,59.8 ; X16.A18@98.5,28.5 98.5,30.9 ; C209.2@98.5,55.2 98.5,54.6 v2(100.6,52.5) ; v10(99,70) 99.2,70.2 C103.2@99.8,70.2 100.2,69.8 C184.2@100.2,68.9 100.3,69 v4(101,69) ; C102.2@99.7,62.2 100.107,62.2 C233.2@101.154,61.154 ; 100.677,61.677 v4(101,62) 101.2,62.2 C197.2@101.2,62.7 ; C199.2@100.746,58.846 100.593,59 v4(100,59) v4(100,58) v4(100,57) 100.2,56.8 100.2,54.8 100.8,54.2 ; v4(101,66) 101.3,65.7 C166.2@101.3,65.3 ; C211.2@101.2,54.2 100.8,54.2 ; 101.8,53.2 100.8,54.2 ; C200.2@101.8,70.2 101.8,69.8 v4(101,69) ; C162.2@102.254,68.254 101.846,68.254 101.1,69 v4(101,69) ; C206.2@102.8,63.8 102.8,63.2 v4(103,63) ; C108.2@104.8,54.7 C155.2@105.8,54.7 ; C196.2@104.8,59.5 C207.2@104.8,60.5 ; C204.2@104.8,71.8 C213.2@104.8,72.8 ; C204.2@104.9,71.9 105.7,71.9 C217.2@105.8,72 ; C215.2@106.7,65 107.7,65 v2(107.9,65.2)
  Solder Side w0.5: v1(56.3,55.6) 56.5,55.8 D13.21@56.5,59.25
  Solder Side w0.6: R207.2@193.6,100.8 R205.2@194.7,100.8 R202.2@195.8,100.8 195.8,101.6 ; v1(224.6,108.5) D15.8@225.555,108.5 225.555,109.845 v1(225.5,109.9) ; C30.2@249.1,100.3 249.1,100.6 C30.2@249.5,101 ; 249.5,101.8 C30.2@249.5,101 ; R223.2@250.6,100.8 249.7,100.8 C30.2@249.5,101
  Solder Side w0.8: v1(56.3,54.5) v1(56.3,55.6) ; 318.75,50.6 C36.2@321.3,50.6 323.85,50.6 ; 318.8,107.3 C188.2@321.35,107.3 323.9,107.3
  other v1: 37.5,35 47.5,35 45,40 50,40 65,40 70,40 75,40 140,40 145,40 150,40 155,40 160,40 165,40 175,40 180,40 185,40 190,40 195,40 200,40 205,40 210,40 215,40 220,40 225,40 230,40 235,40 240,40 245,40 250,40 255,40 260,40 265,40 270,40 275,40 280,40 285,40 290,40 306.7,44.7 37.5,45 47.5,45 67.5,45 147.5,45 152.5,45 157.5,45 162.5,45 167.5,45 172.5,45 177.5,45 182.5,45 187.5,45 192.5,45 197.5,45 202.5,45 207.5,45 212.5,45 217.5,45 222.5,45 227.5,45 232.5,45 237.5,45 242.5,45 247.5,45 252.5,45 257.5,45 262.5,45 267.5,45 272.5,45 277.5,45 282.5,45 287.5,45 306.7,45.9 306.7,47.1 306.7,48.3 59,48.5 45.2,49.5 53.4,49.5 150,50 155,50 160,50 165,50 170,50 175,50 180,50 185,50 190,50 195,50 200,50 205,50 210,50 215,50 220,50 225,50 230,50 235,50 240,50 245,50 250,50 255,50 260,50 265,50 270,50 275,50 280,50 285,50 53.4,53 61,53.5 157.5,55 162.5,55 167.5,55 172.5,55 177.5,55 182.5,55 187.5,55 192.5,55 197.5,55 202.5,55 207.5,55 212.5,55 217.5,55 222.5,55 227.5,55 232.5,55 237.5,55 242.5,55 247.5,55 252.5,55 257.5,55 262.5,55 267.5,55 272.5,55 277.5,55 282.5,55 45,60 78.3,61.7 78.3,62.9 37.5,65 42.5,65 62,66.3 67,66.3 74.1,67.1 77.9,68.6 40,70 305,70 128.8,71.7 127.2,73.1 37.5,75 42.5,75 322.5,75 327.5,75 93.5,78.7 94.5,78.7 95.5,78.7 40,80 139.3,82.4 306.7,82.5 306.7,83.6 306.7,84.8 37.5,85 306.7,86 306.7,87.2 157.4,87.8 207.3,88 243,88.1 249.3,88.1 268.4,88.1 157.4,88.8 213.1,88.9 207.3,89 249.3,89.1 268.4,89.1 263.3,89.3 320,90 184,92.4 78.6,93.8 88.6,93.8 192.8,93.8 198.8,93.8 212.6,93.8 259.6,93.8 263.4,93.8 269.5,93.8 275.7,93.8 243.4,93.9 249.6,93.9 68.5,94 92.4,94 98.6,94 104.8,94 129.4,94 135.6,94 141.8,94 149.4,94 155.6,94 161.8,94 182.6,94 222.6,94 239.5,94 317.5,95 327.5,95 133.8,98.6 97.8,98.7 98.9,98.7 154.5,98.7 156.1,98.7 76.7,100.8 71.3,100.9 153.8,101.8 156.1,101.8 133,101.9 134.3,101.9 135.6,101.9 287.5,105 292.5,105 297.5,105 302.5,105 93.5,109 285,110 290,110 295,110 300,110 325,110 93.5,110.4 87.6,112 88.9,112 67.4,112.3 259.7,112.8 207.5,114.2 277.5,115 282.5,115 287.5,115 292.5,115 297.5,115 312.5,115 317.5,115 322.5,115 206.5,115.5 255.8,115.5 263.4,115.5 45,120 275,120 280,120 285,120 320,120 37.5,125 42.5,125 72.5,125 77.5,125 82.5,125 87.5,125 92.5,125 97.5,125 102.5,125 107.5,125 112.5,125 117.5,125 122.5,125 127.5,125 132.5,125 137.5,125 142.5,125 147.5,125 152.5,125 157.5,125 162.5,125 167.5,125 172.5,125 177.5,125 182.5,125 187.5,125 192.5,125 197.5,125 202.5,125 207.5,125 212.5,125 217.5,125 222.5,125 227.5,125 232.5,125 237.5,125 242.5,125 247.5,125 252.5,125 257.5,125 262.5,125 267.5,125 272.5,125 277.5,125 282.5,125 287.5,125 292.5,125 297.5,125 322.5,125 327.5,125 70,130 75,130 80,130 85,130 90,130 95,130 100,130 105,130 115,130 125,130 130,130 135,130 140,130 145,130 150,130 155,130 160,130 165,130 175,130 185,130 190,130 195,130 200,130 205,130 210,130 215,130 220,130 230,130 240,130 245,130 250,130 255,130 260,130 265,130 270,130 275,130 285,130 290,130 305,130 320,130 49.8,131.9 54.7,131.9
  other v2: 93.2,31.5 98.2,31.5 93.2,32.8 98.2,32.8 94,41.1 96,41.1 112.4,41.5 94,42.225 96,42.225 316.7,45 317.7,45 318.7,45 319.7,45 320.7,45 321.7,45 322.7,45 323.7,45 95.2,45.3 103.3,45.7 316.7,46 317.7,46 318.7,46 319.7,46 320.7,46 321.7,46 322.7,46 323.7,46 316.7,47 317.7,47 318.7,47 319.7,47 320.7,47 321.7,47 322.7,47 323.7,47 104.3,47.2 92.7,47.8 316.7,48 317.7,48 318.7,48 319.7,48 320.7,48 321.7,48 322.7,48 323.7,48 91,48.6 95.8,48.8 316.7,49 317.7,49 318.7,49 319.7,49 320.7,49 321.7,49 322.7,49 323.7,49 103.9,49.8 92.6,50.2 103.2,50.8 105.5,51.1 106,53 104.9,54 113.6,56.7 112.2,58.2 117.1,62.2 316.7,62.8 317.7,62.8 318.7,62.8 319.7,62.8 320.7,62.8 321.7,62.8 322.7,62.8 323.7,62.8 110.9,63.5 113.5,63.5 316.7,63.8 317.7,63.8 318.7,63.8 319.7,63.8 320.7,63.8 321.7,63.8 322.7,63.8 323.7,63.8 316.7,64.8 317.7,64.8 318.7,64.8 319.7,64.8 320.7,64.8 321.7,64.8 322.7,64.8 323.7,64.8 115.6,65.8 316.7,65.8 317.7,65.8 318.7,65.8 319.7,65.8 320.7,65.8 321.7,65.8 322.7,65.8 323.7,65.8 316.7,66.8 317.7,66.8 318.7,66.8 319.7,66.8 320.7,66.8 321.7,66.8 322.7,66.8 323.7,66.8 111.2,68.2 113,68.2 111.2,69.4 113,69.4 108.4,70.2 114,72.7 106.5,72.8 89,75 162.3,77.3 163.7,77.3 168.2,77.3 169.6,77.3 117.5,78.1 118.2,78.8 162.3,78.8 163.7,78.8 168.2,78.8 169.6,78.8 116.3,79.3 125,79.5 126.8,79.5 117,80 125,80.5 126.8,80.5 181.4,80.9 182.8,80.9 316.7,82.2 317.7,82.2 318.7,82.2 319.7,82.2 320.7,82.2 321.7,82.2 322.7,82.2 323.7,82.2 260.4,82.3 181.4,82.6 182.8,82.6 261.1,83 316.7,83.2 317.7,83.2 318.7,83.2 319.7,83.2 320.7,83.2 321.7,83.2 322.7,83.2 323.7,83.2 148.3,83.4 149.3,83.4 181.4,83.4 182.8,83.4 256.9,83.5 259.2,83.5 109.2,84.1 257.6,84.2 259.9,84.2 316.7,84.2 317.7,84.2 318.7,84.2 319.7,84.2 320.7,84.2 321.7,84.2 322.7,84.2 323.7,84.2 255.7,84.7 108.5,84.8 181.4,84.9 182.8,84.9 148.3,85.2 149.3,85.2 316.7,85.2 317.7,85.2 318.7,85.2 319.7,85.2 320.7,85.2 321.7,85.2 322.7,85.2 323.7,85.2 110.5,85.4 256.4,85.4 109.8,86.1 316.7,86.2 317.7,86.2 318.7,86.2 319.7,86.2 320.7,86.2 321.7,86.2 322.7,86.2 323.7,86.2 316.7,101.7 317.7,101.7 318.7,101.7 319.7,101.7 320.7,101.7 321.7,101.7 322.7,101.7 323.7,101.7 316.7,102.7 317.7,102.7 318.7,102.7 319.7,102.7 320.7,102.7 321.7,102.7 322.7,102.7 323.7,102.7 316.7,103.7 317.7,103.7 318.7,103.7 319.7,103.7 320.7,103.7 321.7,103.7 322.7,103.7 323.7,103.7 316.7,104.7 317.7,104.7 318.7,104.7 319.7,104.7 320.7,104.7 321.7,104.7 322.7,104.7 323.7,104.7 316.7,105.7 317.7,105.7 318.7,105.7 319.7,105.7 320.7,105.7 321.7,105.7 322.7,105.7 323.7,105.7
  other v4: 88.2,50.5 90,50.5 88.2,51.9
  other v7: 84,57
  other v8: 97,50.5
  other v10: 90,53 94.025,53.1 87,70
  other v11: 127.4,92.5 261.4,92.5 241.7,92.6 143.5,95.5 204.7,98.5 55.6,125.044 55.6,127.044
  other v12: 96,31.5 80.5,32 84,32 87,32 96,32.8 69,36 73,36 80.5,36 84,36 87,36 91,36
  other v14: 92,44.9 117.9,72.1 256,76.3 153.7,77 174.3,83.7
  other v16: 94,36
I2C_RESET: D11.40 D16.3 R234.2 | length 31
  Component Side w0.15: D11.40@63.75,116.95 63.75,116.05 64.2,115.6 v1(64.2,114.4) ; R234.2@83.6,112 v1(84.6,112) ; v1@84.605,112.005 D16.3@85.9,112.005
  Inner Layer 1 w0.15: v1(84.6,112) v1(84.6,116.1)
  Inner Layer 2 w0.15: v1(64.2,114.4) 64.7,114.9 64.7,115.9 65.1,116.3 83.9,116.3 84.1,116.1 v1(84.6,116.1)
INPUTPWR: C36.1 C37.1 C38.1 C46.1 C47.1 C58.1 C59.1 C70.1 C71.1 C188.1 D1.1 D2.1 D3.1 D4.1 R1.1 R30.1 R34.1 R49.1 R55.1 X10.1 Z1.2 | length 24.3
  Component Side w0.2: R55.1@308,87.2 310,89.2 v3(310.1,89.2) ; R49.1@308,106.8 R49.1@308.1,106.9 ; R49.1@308.1,106.7 R49.1@308.1,106.9 ; v3@309.9,108.7 R49.1@308.1,106.9
  Solder Side w0.2: v3(310.1,69.8) 308.95,69.8 R30.1@308.45,70.3 R34.1@308.45,72.5 308.55,72.4 v3(310.1,72.4)
  Solder Side w0.4: X10.1@295,118 297.3,120.3 300.1,120.3 301.8,118.6 Z1.2@301.8,116.1 ; R1.1@308.3,108.75 v3@310.05,108.75
  other v3: 310,52 311.3,52 310,53.3 311.3,53.3 310,54.6 311.3,54.6 310,55.9 311.3,55.9 311.4,69.8 310.1,71.1 311.4,71.1 311.4,72.4 310.1,73.7 311.4,73.7 311.4,89.2 310.1,90.5 311.4,90.5 310.1,91.8 311.4,91.8 310.1,93.1 311.4,93.1 310.1,108.7 311.4,108.7 310.1,110 311.4,110 310.1,111.3 311.4,111.3 310.1,112.6 311.4,112.6
M_SGMII_L0DATI_0_N: C81.1 X1.57 | length 39.7
  Component Side w0.15: X1.57@85.315,91.135 85.315,92.36 85.41,92.455 85.41,92.928 85.892,93.41 86.628,93.41 87.21,92.828 87.21,86.728 90.628,83.31 97.69,83.31 101.89,79.11 105.418,79.11 107.565,76.963 107.565,72.345 C81.1@107.91,72
M_SGMII_L0DATI_0_P: C80.1 X1.59 | length 41.3
  Component Side w0.15: X1.59@85.815,91.135 85.815,92.36 85.72,92.455 85.72,92.8 86.02,93.1 86.5,93.1 86.9,92.7 86.9,89.6 cw(c86.6,89.6) 86.6,89.3 86.232,89.3 ccw(c86.232,89) 86.232,88.7 86.6,88.7 cw(c86.6,88.4) 86.6,88.1 86.318,88.1 ccw(c86.318,87.8) 86.318,87.5 86.6,87.5 cw(c86.6,87.2) 86.9,87.2 86.9,86.6 90.5,83 97.562,83 101.762,78.8 105.29,78.8 107.255,76.835 107.255,72.345 C80.1@106.91,72
M_SGMII_L0DATI_1_N: C84.1 X8.117 | length 60.6
  Solder Side w0.15: X8.117@71.81,91.135 71.81,92.36 71.715,92.455 71.715,93.028 71.233,93.51 70.472,93.51 69.89,92.928 69.89,88.772 73.272,85.39 80.872,85.39 81.672,84.59 90.582,84.59 94.482,80.69 104.51,80.69 108.99,76.21 108.99,69.99 108.562,69.562 107.969,69.562 C84.1@107.629,69.902
M_SGMII_L0DATI_1_P: C82.1 X8.119 | length 61.7
  Solder Side w0.15: X8.119@71.31,91.135 71.31,92.36 71.405,92.455 71.405,92.9 71.105,93.2 70.6,93.2 70.2,92.8 70.2,88.9 70.5,88.6 ccw(c70.712,88.812) 70.924,88.6 71.263,88.938 cw(c71.475,88.726) 71.687,88.514 71.349,88.176 ccw(c71.561,87.964) 71.349,87.751 73.4,85.7 81,85.7 81.8,84.9 90.71,84.9 94.61,81 104.638,81 109.3,76.338 109.3,69.862 108.691,69.252 107.969,69.252 C82.1@107.629,68.912
M_SGMII_L0DATI_2_N: C185.1 X1.117 | length 26
  Component Side w0.15: X1.117@105.32,91.135 105.32,89.91 105.415,89.815 105.415,81.047 109.2,77.262 109.2,68.38 108.8,67.98 108.245,67.98 C185.1@107.9,68.325
M_SGMII_L0DATI_2_P: C186.1 X1.119 | length 27.1
  Component Side w0.15: X1.119@105.82,91.135 105.82,89.91 105.725,89.815 105.725,89.152 ccw(c105.985,89.152) 105.985,88.892 cw(c105.985,88.632) 106.245,88.632 106.245,88.552 cw(c105.985,88.552) 105.985,88.292 ccw(c105.985,88.032) 105.725,88.032 105.725,81.175 109.51,77.39 109.51,68.252 108.928,67.67 108.245,67.67 C186.1@107.9,67.325
M_SGMII_L0DATI_3_N: C191.1 X8.57 | length 46
  Solder Side w0.15: X8.57@91.815,91.135 91.815,92.36 91.72,92.455 91.72,93.018 91.328,93.41 90.672,93.41 90,92.738 90,89.562 95.872,83.69 103.51,83.69 110.3,76.9 110.3,69.3 108.655,67.655 105.845,67.655 C191.1@105.5,68
M_SGMII_L0DATI_3_P: C192.1 X8.59 | length 47.2
  Solder Side w0.15: X8.59@91.315,91.135 91.315,92.36 91.41,92.455 91.41,92.89 91.2,93.1 90.8,93.1 90.31,92.61 90.31,89.69 92.8,87.2 ccw(c93.012,87.412) 93.224,87.2 93.562,87.538 cw(c93.774,87.326) 93.987,87.114 93.649,86.776 ccw(c93.861,86.564) 93.649,86.351 96,84 103.638,84 110.61,77.028 110.61,69.172 108.783,67.345 105.845,67.345 C192.1@105.5,67
M_SGMII_L1DATI_0_N: C89.1 R17.2 R21.1 X2.57 | length 56.9
  Component Side w0.15: v8(117,79.3) 117.281,79.3 121.391,83.41 126.61,83.41 128.6,85.4 138.804,85.4 138.962,85.558 139.462,85.558 139.62,85.4 140.12,85.4 140.31,85.59 140.81,85.59 141,85.4 141.6,85.4 142.395,86.195 142.395,87.605 R17.2@142,88 142.395,88.395 142.395,88.705 R21.1@142,89.1 142.075,89.175 142.085,89.175 142.41,89.5 142.41,89.815 142.315,89.91 X2.57@142.315,91.135
  Solder Side w0.15: C89.1@109.2,62.3 109.545,61.955 110.5,61.955 112.945,64.4 115.1,64.4 116.5,65.8 116.5,78.519 117,79.019 v8(117,79.3)
M_SGMII_L1DATI_0_P: C87.1 R18.2 R22.1 X2.59 | length 57.1
  Component Side w0.15: v8(117.5,78.8) 117.5,79.081 121.519,83.1 126.738,83.1 128.728,85.09 141.728,85.09 142.705,86.067 142.705,87.605 R18.2@143.1,88 142.705,88.395 142.705,88.705 R22.1@143.1,89.1 142.72,89.48 142.72,89.815 142.815,89.91 X2.59@142.815,91.135
  Solder Side w0.15: C87.1@109.2,61.3 109.545,61.645 110.628,61.645 113.073,64.09 115.228,64.09 116.81,65.672 116.81,78.39 117.219,78.8 v8(117.5,78.8)
M_SGMII_L1DATI_1_N: C62.1 R60.2 R64.1 X3.117 | length 45.4
  Component Side w0.15: C62.1@112.559,61.183 112.899,60.843 113.643,60.843 114.1,61.3 114.1,62 125.745,73.645 125.745,79.755 v2(125.5,80)
  Solder Side w0.15: v2(125.5,80) 125.745,80.245 125.745,84.345 126.795,85.395 126.795,86.605 R64.1@126.4,87 126.795,87.395 126.795,87.705 R60.2@126.4,88.1 126.79,88.49 126.79,89.472 125.69,90.572 125.69,92.728 126.472,93.51 128.233,93.51 128.715,93.028 128.715,92.455 128.81,92.36 X3.117@128.81,91.135
M_SGMII_L1DATI_1_P: C60.1 R61.2 R65.1 X3.119 | length 46.5
  Component Side w0.15: C60.1@112.559,60.193 112.899,60.533 113.771,60.533 114.41,61.172 114.41,61.872 126.055,73.517 126.055,79.755 v2(126.3,80)
  Solder Side w0.15: v2(126.3,80) 126.055,80.245 126.055,84.217 127.105,85.267 127.105,86.605 R65.1@127.5,87 127.105,87.395 127.105,87.705 R61.2@127.5,88.1 127.1,88.5 127.1,89.6 126,90.7 126,91 cw(c126.3,91) 126.3,91.3 126.776,91.3 ccw(c126.776,91.6) 127.076,91.6 ccw(c126.776,91.6) 126.776,91.9 126.3,91.9 cw(c126.3,92.2) 126,92.2 126,92.6 126.6,93.2 128.105,93.2 128.405,92.9 128.405,92.455 128.31,92.36 X3.119@128.31,91.135
M_SGMII_L1DATI_2_N: C93.1 R51.2 R62.1 X2.117 | length 70.7
  Component Side w0.15: C93.1@110,62.9 110.345,62.555 111,62.555 123.89,75.445 123.89,80.728 124.662,81.5 131,81.5 133.41,83.91 144.782,83.91 146.972,86.1 161.615,86.1 162.415,86.9 162.415,87.605 R62.1@162.02,88 162.415,88.395 162.415,88.705 R51.2@162.02,89.1 162.415,89.495 162.415,89.815 162.32,89.91 X2.117@162.32,91.135
M_SGMII_L1DATI_2_P: C91.1 R59.2 R63.1 X2.119 | length 71.8
  Component Side w0.15: C91.1@110,61.9 110.345,62.245 111.128,62.245 124.2,75.317 124.2,80.6 124.79,81.19 131.128,81.19 133.538,83.6 144.91,83.6 147.1,85.79 161.743,85.79 161.853,85.9 cw(c162.03,85.723) 162.207,85.9 162.223,85.884 ccw(c162.399,86.061) 162.576,85.884 162.647,85.955 ccw(c162.47,86.132) 162.647,86.309 162.631,86.324 cw(c162.808,86.501) 162.631,86.678 162.725,86.772 162.725,87.605 R63.1@163.12,88 162.725,88.395 162.725,88.705 R59.2@163.12,89.1 162.725,89.495 162.725,89.815 162.82,89.91 X2.119@162.82,91.135
M_SGMII_L1DATI_3_N: C68.1 R19.2 R23.1 X3.57 | length 85.7
  Solder Side w0.15: C68.1@109.2,60.2 109.545,59.855 110.455,59.855 113.41,62.81 115.7,62.81 119,66.11 119,86.238 122.08,89.318 122.08,93.68 123.59,95.19 123.59,96.928 130.467,103.805 142.605,103.805 R19.2@143,104.2 143.395,103.805 143.705,103.805 R23.1@144.1,104.2 144.495,103.805 145.128,103.805 145.7,103.233 145.7,93.91 146.1,93.51 148.238,93.51 148.72,93.028 148.72,92.455 148.815,92.36 X3.57@148.815,91.135
M_SGMII_L1DATI_3_P: C67.1 R20.2 R24.1 X3.59 | length 86.9
  Solder Side w0.15: C67.1@109.2,59.2 109.545,59.545 110.583,59.545 113.538,62.5 115.828,62.5 119.31,65.982 119.31,86.11 122.39,89.19 122.39,93.552 123.9,95.062 123.9,96.8 130.595,103.495 142.605,103.495 R20.2@143,103.1 143.395,103.495 143.705,103.495 R24.1@144.1,103.1 144.495,103.495 145,103.495 145.39,103.105 145.39,95.6 cw(c145.09,95.6) 145.09,95.3 144.611,95.3 ccw(c144.611,95) 144.311,95 ccw(c144.611,95) 144.611,94.7 145.09,94.7 cw(c145.09,94.4) 145.39,94.4 145.39,93.782 145.972,93.2 148.11,93.2 148.41,92.9 148.41,92.455 148.315,92.36 X3.59@148.315,91.135
M_SGMII_L2DATI_0_N: C79.1 X4.57 | length 107.6
  Component Side w0.15: C79.1@108.3,54.8 108.645,54.455 109.8,54.455 110.345,55 120.2,55 142.81,77.61 149.01,77.61 153,81.6 165.262,81.6 172.462,88.8 199.01,88.8 199.41,89.2 199.41,89.815 199.315,89.91 X4.57@199.315,91.135
M_SGMII_L2DATI_0_P: C77.1 X4.59 | length 108.2
  Component Side w0.15: C77.1@108.3,53.8 108.645,54.145 109.928,54.145 110.473,54.69 120.328,54.69 142.938,77.3 149.138,77.3 153.128,81.29 165.39,81.29 172.59,88.49 197.872,88.49 197.995,88.367 198.505,88.367 198.628,88.49 199.138,88.49 199.72,89.072 199.72,89.815 199.815,89.91 X4.59@199.815,91.135
M_SGMII_L2DATI_1_N: C73.1 X5.117 | length 97.1
  Solder Side w0.15: C73.1@108.2,56.9 108.545,56.555 111.455,56.555 113.11,58.21 126.472,58.21 150.962,82.7 176.09,82.7 182.7,89.31 182.7,92.7 183.51,93.51 185.233,93.51 185.715,93.028 185.715,92.455 185.81,92.36 X5.117@185.81,91.135
M_SGMII_L2DATI_1_P: C72.1 X5.119 | length 96.9
  Solder Side w0.15: C72.1@108.2,55.9 108.545,56.245 111.583,56.245 113.238,57.9 126.6,57.9 151.09,82.39 176.218,82.39 183.01,89.182 183.01,89.672 183.2,89.862 183.2,90.362 183.01,90.552 183.01,91.072 183.26,91.322 183.26,91.822 183.01,92.072 183.01,92.572 183.638,93.2 185.105,93.2 185.405,92.9 185.405,92.455 185.31,92.36 X5.119@185.31,91.135
M_SGMII_L2DATI_2_N: C97.1 X4.117 | length 127.5
  Component Side w0.15: v8(182.1,84.5) 182.295,84.305 200.905,84.305 202.4,85.8 216.915,85.8 219.415,88.3 219.415,89.815 219.32,89.91 X4.117@219.32,91.135
  Solder Side w0.15: C97.1@112.354,50.954 112.834,50.954 113.79,51.909 113.79,55.228 115.272,56.71 127.172,56.71 151.672,81.21 176.7,81.21 179.795,84.305 181.905,84.305 v8(182.1,84.5)
M_SGMII_L2DATI_2_P: C98.1 X4.119 | length 127.9
  Component Side w0.15: v8(182.1,83.8) 182.295,83.995 201.033,83.995 202.528,85.49 217.043,85.49 218.865,87.312 219.039,87.312 219.4,87.673 219.4,87.847 219.725,88.172 219.725,89.815 219.82,89.91 X4.119@219.82,91.135
  Solder Side w0.15: C98.1@113.054,50.254 113.054,50.734 114.1,51.781 114.1,55.1 115.4,56.4 127.3,56.4 151.8,80.9 176.828,80.9 179.923,83.995 181.905,83.995 v8(182.1,83.8)
M_SGMII_L2DATI_3_N: C64.1 X5.57 | length 128.9
  Component Side w0.15: C64.1@102.954,49.746 102.954,49.266 104.11,48.11 109.51,48.11 113.11,51.71 123.11,51.71 123.91,52.51 125.6,54.2 125.6,57.3 144.41,76.11 164.41,76.11 166.505,78.205 168.705,78.205 v8(168.9,78.4)
  Solder Side w0.15: v8(168.9,78.4) 169.095,78.205 185.667,78.205 188.362,80.9 195.7,80.9 203.89,89.09 203.89,92.928 204.472,93.51 205.238,93.51 205.72,93.028 205.72,92.455 205.815,92.36 X5.57@205.815,91.135
M_SGMII_L2DATI_3_P: C76.1 X5.59 | length 129.8
  Component Side w0.15: C76.1@102.254,49.046 102.734,49.046 103.981,47.8 109.638,47.8 113.238,51.4 123.238,51.4 124.038,52.2 125.91,54.072 125.91,57.172 144.538,75.8 164.538,75.8 166.633,77.895 168.705,77.895 v8(168.9,77.7)
  Solder Side w0.15: v8(168.9,77.7) 169.095,77.895 185.795,77.895 188.49,80.59 195.828,80.59 202.932,87.693 cw(c203.144,87.481) 203.356,87.693 203.513,87.537 ccw(c203.725,87.749) 203.937,87.537 ccw(c203.725,87.749) 203.937,87.961 203.78,88.118 cw(c203.993,88.33) 203.78,88.542 204.2,88.962 204.2,92.8 204.6,93.2 205.11,93.2 205.41,92.9 205.41,92.455 205.315,92.36 X5.59@205.315,91.135
M_SGMII_L3DATI_0_N: C49.1 R68.2 R70.1 X6.57 | length 190.1
  Component Side w0.15: C49.1@95.325,51.3 94.98,50.955 94.98,50.12 95.4,49.7 96.238,49.7 102.338,43.6 110.7,43.6 114.9,47.8 125.5,47.8 130.1,52.4 130.1,55.3 146.41,71.61 170.71,71.61 179.31,80.21 183.41,80.21 186.01,82.81 201.51,82.81 203.01,84.31 253.905,84.31 256.395,86.8 256.395,87.605 R70.1@256,88 256.395,88.395 256.395,88.705 R68.2@256,89.1 256.075,89.175 256.085,89.175 256.41,89.5 256.41,89.815 256.315,89.91 X6.57@256.315,91.135
M_SGMII_L3DATI_0_P: C48.1 R69.2 R71.1 X6.59 | length 191.2
  Component Side w0.15: C48.1@94.325,51.3 94.67,50.955 94.67,49.992 95.272,49.39 96.11,49.39 102.21,43.29 110.828,43.29 115.028,47.49 125.628,47.49 130.41,52.272 130.41,55.172 146.538,71.3 170.838,71.3 179.438,79.9 183.538,79.9 186.138,82.5 201.638,82.5 203.138,84 254.033,84 255.255,85.221 255.489,85.221 255.849,85.582 255.849,85.816 256.705,86.672 256.705,87.605 R71.1@257.1,88 256.705,88.395 256.705,88.705 R69.2@257.1,89.1 256.72,89.48 256.72,89.815 256.815,89.91 X6.59@256.815,91.135
M_SGMII_L3DATI_1_N: C55.1 R112.2 R114.1 X7.117 | length 170.4
  Solder Side w0.15: C55.1@101.554,46.746 101.554,46.266 103.919,43.9 111.6,43.9 116.11,48.41 125.81,48.41 152.61,75.21 186.872,75.21 189.562,77.9 196.862,77.9 203.262,84.3 239.262,84.3 240.295,85.333 240.295,86.605 R112.2@239.9,87 240.295,87.395 240.295,87.705 R114.1@239.9,88.1 240.295,88.495 240.295,92.833 240.972,93.51 242.233,93.51 242.715,93.028 242.715,92.455 242.81,92.36 X7.117@242.81,91.135
M_SGMII_L3DATI_1_P: C54.1 R113.2 R115.1 X7.119 | length 171.2
  Solder Side w0.15: C54.1@100.854,46.046 101.334,46.046 103.791,43.59 111.728,43.59 116.238,48.1 125.938,48.1 152.738,74.9 187,74.9 189.69,77.59 196.99,77.59 203.39,83.99 239.39,83.99 240.605,85.205 240.605,86.605 R113.2@241,87 240.605,87.395 240.605,87.705 R115.1@241,88.1 240.605,88.495 240.605,91 cw(c240.905,91) 240.905,91.3 241.127,91.3 ccw(c241.127,91.6) 241.427,91.6 ccw(c241.127,91.6) 241.127,91.9 240.905,91.9 cw(c240.905,92.2) 240.605,92.2 240.605,92.705 241.1,93.2 242.105,93.2 242.405,92.9 242.405,92.455 242.31,92.36 X7.119@242.31,91.135
M_SGMII_L3DATI_2_N: C88.1 R84.2 R86.1 X6.117 | length 208.4
  Component Side w0.15: v8(256.4,84.7) 256.681,84.7 257.481,85.5 275.095,85.5 276.395,86.8 276.395,87.605 R86.1@276,88 276.395,88.395 276.395,88.705 R84.2@276,89.1 276.415,89.515 276.415,89.815 276.32,89.91 X6.117@276.32,91.135
  Solder Side w0.15: C88.1@98.154,48.546 98.154,48.066 98.71,47.509 98.71,46.69 103,42.4 127.7,42.4 128.4,43.1 128.4,48.738 153.372,73.71 187.51,73.71 190.21,76.41 197.5,76.41 203.89,82.8 254.781,82.8 256.4,84.419 v8(256.4,84.7)
M_SGMII_L3DATI_2_P: C86.1 R85.2 R87.1 X6.119 | length 209.3
  Component Side w0.15: v8(256.9,84.2) 256.9,84.481 257.609,85.19 275.223,85.19 275.658,85.625 275.859,85.625 276.22,85.986 276.22,86.187 276.705,86.672 276.705,87.605 R87.1@277.1,88 276.705,88.395 276.705,88.705 R85.2@277.1,89.1 276.725,89.475 276.725,89.815 276.82,89.91 X6.119@276.82,91.135
  Solder Side w0.15: C86.1@97.454,47.846 97.934,47.846 98.4,47.381 98.4,46.562 102.872,42.09 127.828,42.09 128.71,42.972 128.71,48.61 153.5,73.4 187.638,73.4 190.338,76.1 197.628,76.1 204.018,82.49 254.909,82.49 256.619,84.2 v8(256.9,84.2)
M_SGMII_L3DATI_3_N: C92.1 R92.2 R96.1 X7.57 | length 203
  Component Side w0.15: C92.1@95.354,47.846 95.354,47.366 95.91,46.81 97.09,46.81 101.8,42.1 111.1,42.1 115.51,46.51 126.31,46.51 131.6,51.8 131.6,54.5 147.21,70.11 171.51,70.11 180.11,78.71 184.11,78.71 186.71,81.31 202.21,81.31 203.691,82.791 259.472,82.791 259.9,83.219 v8(259.9,83.5)
  Solder Side w0.15: v8(259.9,83.5) 260.181,83.5 261.495,84.814 261.495,86.605 R96.1@261.1,87 261.495,87.395 261.495,87.705 R92.2@261.1,88.1 261.495,88.495 261.495,89.205 261.1,89.6 260.462,89.6 259.9,90.162 259.9,92.6 260.81,93.51 262.238,93.51 262.72,93.028 262.72,92.455 262.815,92.36 X7.57@262.815,91.135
